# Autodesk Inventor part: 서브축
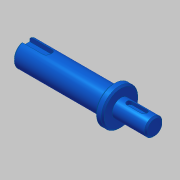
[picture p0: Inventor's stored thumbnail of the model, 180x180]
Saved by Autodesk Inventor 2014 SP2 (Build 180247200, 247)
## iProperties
Created: 2018-09
Part Number: 서브축
Document SubType Name: Modeling
Density: 7.86 g/cm^3
Material: 강철, 연강
Appearance: 청록색
Mass: 142.802 g
Surface Area: 54.7946 cm^2
Volume: 18.1682 cm^3
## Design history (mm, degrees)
sketch "스케치1"
  geometry: L1 (-18.818, -7)-(-18.818, 7) reference; L2 (-41.331, -13.5)-(-41.331, 13.5) reference; L3 (-46.5, 12.249)-(-46.5, -12.249) reference; L4 (-18.331, 0)-(-106.5, 0); L5 (-18.331, 0)-(-18.331, -6); L6 (-18.331, -6)-(-41.331, -6); L7 (-41.331, -12.5)-(-46.5, -12.5); L8 (-46.5, -8.5)-(-106.5, -8.5); L9 (-106.5, -8.5)-(-106.5, 0); L10 (-46.5, -8.5)-(-46.5, -12.5); L11 (-41.331, -6)-(-41.331, -12.5); 2 further points
  constraints: 17 end point, 5 point on line, 3 parallel, 3 perpendicular, 2 collinear, 1 midpoint
  dimensions: "d0" = 23 distance between parallel lines of L2 L5; "d1" = 12 diameter of L6 L4; "d2" = 25 diameter of L7 L4; "d3" = 17 diameter of L8 L4; "d4" = 60 distance of L8.start L8.end
revolve "회전1" sketch "스케치1" stored, may be unused: angle "d5" = 90 deg
chamfer "모따기1" distance "d6" = 1; stored, may be unused: second distance "d7" = 2, angle "d8" = 45 deg
node "작업 평면1"
sketch "스케치2"
  geometry: L1 (11.5, 5)-(11.5, -5) reference; L2 (-5.5, -2)-(4.5, -2); L3 (4.5, 2)-(-5.5, 2); A1 r 2 centre (4.5, 0) between (4.5, -2) and (4.5, 2); A2 r 2 centre (-5.5, 0) between (-5.5, 2) and (-5.5, -2); 2 further points
  constraints: 4 end point, 4 point on circle, 4 tangent, 2 centre point, 1 horizontal alignment, 1 midpoint, 1 parallel, 1 perpendicular
  dimensions: "d9" = 4 distance between parallel lines of L2 L3; "d10" = 14 dimension on A1 A2; "d11" = 5 distance edge to line of A1 L1
extrude "돌출1" cut sketch "스케치2" distance "d12" = 2.5; taper "d13" = 0 deg
node "작업 평면2"
sketch "스케치3"
  geometry: L1 (-30, -7.5)-(-30, 7.5) reference; L2 (-30, 3)-(-15, 3); L3 (-15, -3)-(-30, -3); A1 r 3 centre (-15, 0) between (-15, -3) and (-15, 3); 2 further points
  constraints: 4 end point, 2 perpendicular, 2 point on circle, 2 point on line, 2 tangent, 1 centre point, 1 horizontal alignment, 1 midpoint
  dimensions: "d14" = 6 distance between parallel lines of L3 L2; "d15" = 18 dimension on A1 L1
extrude "돌출2" cut sketch "스케치3" distance "d16" = 3.5; taper "d17" = 0 deg
node "솔리드1"
node "참조1"
node "참조2"
node "참조3"
